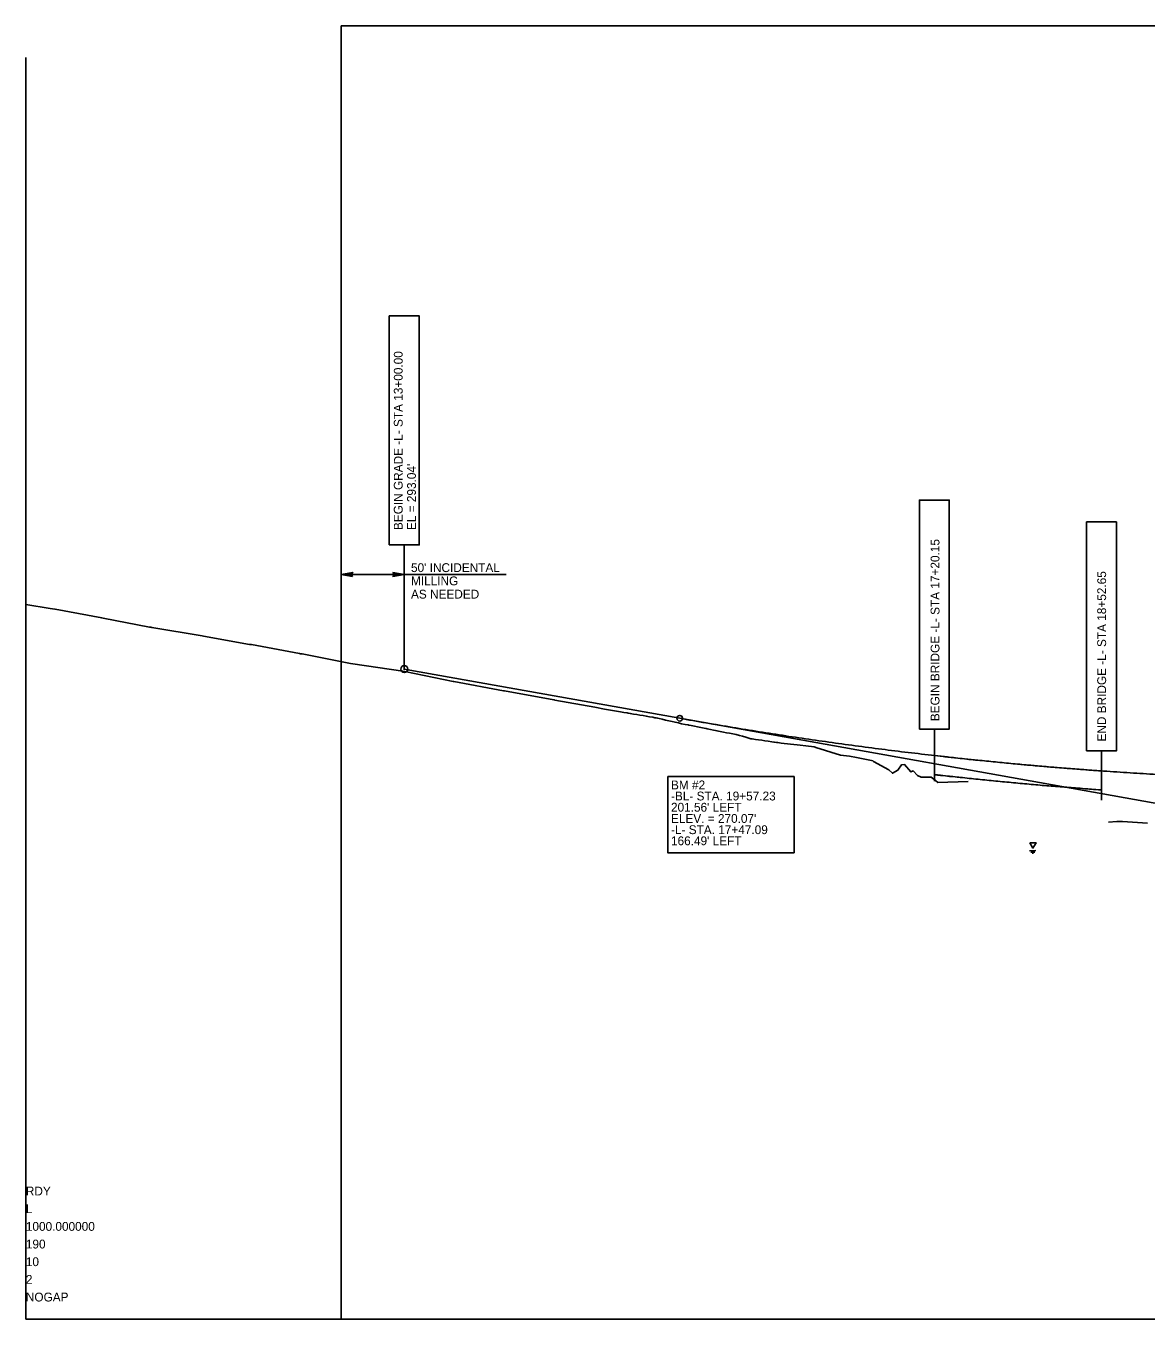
# Model space of a CAD drawing. Extents: x 10000 to 11818, y 10000 to 11025.
# Drawn here: x 10000 to 10888, y 10000 to 11025 of the extents above; entities that cross this region are included whole.
import ezdxf

# ---------------------------------------------------------------- set-up
doc = ezdxf.new("R2010")
doc.units = 0
for name, color, linetype in [('Default', 7, 'Continuous'), ('Exist Profile Cell', 7, 'Continuous'), ('Exist Vertical Profile Ground Line', 7, 'Continuous'), ('Prop Grid Mask', 7, 'Continuous'), ('Prop Hydrographic FEMA Cross Section', 7, 'Continuous'), ('Prop Shade Light', 7, 'Continuous'), ('Prop Terminator CELL', 7, 'Continuous'), ('Prop Vertical Profile Curve Label', 7, 'Continuous'), ('Prop Vertical Profile Grade', 7, 'Continuous'), ('Prop VPI Label', 7, 'Continuous'), ('Sheet Layout Profile Border', 7, 'Continuous')]:
    doc.layers.add(name, color=color, linetype=linetype)

msp = doc.modelspace()

# ---------------------------------------------------------------- linework, layer by layer
at = {"layer": 'Default'}
for p, q in [((10852.6, 10414.4), (10852.6, 10411.4)), ((10795.7, 10371.2), (10800.7, 10371.3)), ((10796.7, 10370.2), (10799.7, 10370.2)), ((10797.7, 10369.2), (10798.7, 10369.2))]:
    msp.add_line(p, q, dxfattribs=at)
msp.add_lwpolyline([(10795.8, 10377.6), (10800.8, 10377.6), (10798.3, 10373.3)], close=True, dxfattribs=at)
at = {"layer": 'Exist Profile Cell'}
for q in [(10000, 11000), (11817.5, 10000), (10000, 10000)]:
    msp.add_line((10000, 10000), q, dxfattribs=at)
at = {"layer": 'Exist Vertical Profile Ground Line'}
for p, q in [((10722.9, 10425.4), (10747, 10426)), ((10858.1, 10393.9), (10858.3, 10394))]:
    msp.add_line(p, q, dxfattribs=at)
for points in [[(10000, 10566.3), (10019.2, 10563.2), (10021.1, 10563), (10023.1, 10562.6), (10060.1, 10555.7), (10061.4, 10555.5), (10098.1, 10548.5), (10099, 10548.3), (10099.9, 10548.1), (10139.8, 10541.5), (10140.9, 10541.3), (10177.2, 10534.8), (10178.8, 10534.6), (10216.8, 10527.6), (10217.8, 10527.4), (10218.9, 10527.2), (10257.3, 10519.7), (10259.3, 10519.4), (10298.8, 10513.6), (10299.8, 10513.4), (10300.4, 10513.3), (10338.8, 10505.4), (10339.2, 10505.3), (10378.7, 10498), (10379.1, 10498), (10379.4, 10497.9), (10418.5, 10490.9), (10419, 10490.8), (10419.4, 10490.7), (10451.1, 10484.9), (10458.8, 10483.4), (10471.5, 10481.3), (10474, 10480.9), (10476.6, 10480.5), (10477.4, 10480.3), (10479.1, 10480.1), (10481.7, 10479.6), (10484.2, 10479.2), (10486.7, 10478.7), (10489.3, 10478.3), (10491.8, 10477.9), (10494.4, 10477.4), (10496.9, 10477), (10498.5, 10476.7), (10499.6, 10476.5), (10500.9, 10476.2), (10502, 10476), (10504.5, 10475.4), (10507.1, 10474.8), (10509.6, 10474.2), (10512.2, 10473.7), (10514.7, 10473.1), (10517.3, 10472.5), (10519.8, 10471.9), (10522.6, 10471.3), (10524.9, 10470.9), (10525.5, 10470.8), (10527.4, 10470.4), (10530, 10469.9), (10532.5, 10469.4), (10535.1, 10468.9), (10537.6, 10468.4), (10539.3, 10468), (10540.1, 10467.8), (10542.7, 10467.3), (10545.2, 10466.8), (10546.7, 10466.5), (10547.8, 10466.3), (10550.3, 10465.8), (10552.9, 10465.3), (10555.4, 10464.8), (10557.9, 10464.3), (10560.5, 10463.8), (10563, 10463.3), (10565.8, 10462.7), (10568.1, 10462), (10570.6, 10461.3), (10573.2, 10460.5), (10574.8, 10460), (10575.7, 10459.9), (10578.3, 10459.5), (10580.8, 10459.1), (10583.4, 10458.8), (10585.9, 10458.4), (10588.4, 10458), (10591.2, 10457.6), (10593, 10457.3), (10593.5, 10457.2), (10594.9, 10457.1), (10596.1, 10456.9), (10598.6, 10456.6), (10601.2, 10456.3), (10603.7, 10456), (10606.2, 10455.7), (10608.8, 10455.4), (10611.3, 10455.1), (10613.9, 10454.8), (10618.4, 10454.3), (10624.8, 10453.5), (10625.8, 10453.2), (10626.2, 10453.1), (10645.7, 10446.9), (10652.9, 10446.1), (10658.4, 10445.1), (10670.3, 10442.7), (10671.3, 10442.4), (10671.9, 10441.9), (10684.2, 10435.4), (10686.9, 10432.7), (10691.1, 10435), (10694.1, 10439.2), (10696.6, 10439.5), (10701.4, 10433.7), (10703.3, 10434.5), (10706.8, 10430.9), (10709.6, 10429.5), (10717.6, 10429.5), (10721.2, 10426.9), (10722.9, 10425.4)], [(10858.3, 10394), (10864.8, 10394.4), (10869.3, 10394.5), (10889, 10393.2)]]:
    msp.add_lwpolyline(points, dxfattribs=at)
at = {"layer": 'Prop Grid Mask'}
for points in [[(10288.1, 10613.6), (10311.9, 10613.6), (10311.9, 10795.1), (10288.1, 10795.1)], [(10708.3, 10467.7), (10732, 10467.7), (10732, 10649.2), (10708.3, 10649.2)], [(10840.8, 10450.4), (10864.5, 10450.4), (10864.5, 10631.9), (10840.8, 10631.9)], [(10508.8, 10430), (10609, 10430), (10609, 10369.6), (10508.8, 10369.6)]]:
    msp.add_lwpolyline(points, close=True, dxfattribs=at)
at = {"layer": 'Prop Hydrographic FEMA Cross Section'}
for p, q in [((10720.2, 10446.4), (10720.2, 10426.3)), ((10852.6, 10434.4), (10852.6, 10414.4))]:
    msp.add_line(p, q, dxfattribs=at)
at = {"layer": 'Prop Shade Light'}
for p, q in [((10720.2, 10446.7), (10720.2, 10431.3)), ((10852.6, 10419.4), (10852.6, 10434.5))]:
    msp.add_line(p, q, dxfattribs=at)
for points in [[(10852.6, 10434.5), (10846.3, 10434.9), (10839.8, 10435.4), (10833.3, 10435.9), (10826.3, 10436.4), (10819.3, 10437), (10812.3, 10437.6), (10805.3, 10438.2), (10798.3, 10438.8), (10791.3, 10439.4), (10784.3, 10440.1), (10777.3, 10440.7), (10770.3, 10441.4), (10763.3, 10442.1), (10756.3, 10442.8), (10749.3, 10443.5), (10742.3, 10444.2), (10735.3, 10445), (10728.3, 10445.8), (10728.1, 10445.8), (10728, 10445.8), (10720.2, 10446.7)], [(10720.2, 10431.3), (10734.5, 10430), (10741.1, 10429.3), (10747.7, 10428.6), (10754.8, 10427.9), (10761.8, 10427.2), (10768.8, 10426.5), (10775.9, 10425.8), (10782.9, 10425.1), (10789.9, 10424.5), (10797, 10423.8), (10804, 10423.2), (10811, 10422.6), (10818.1, 10422.1), (10825.1, 10421.5), (10832.1, 10421), (10839, 10420.4), (10845.9, 10419.9), (10852.6, 10419.4)]]:
    msp.add_open_spline(points, degree=3, dxfattribs=at)
at = {"layer": 'Prop Terminator CELL'}
for points in [[(10259, 10588.6), (10250, 10590.2), (10259.1, 10591.8), (10257.9, 10590.2)], [(10291, 10591.7), (10300, 10590.2), (10291, 10588.6), (10292.1, 10590.2)]]:
    msp.add_lwpolyline(points, close=True, dxfattribs=at)
at = {"layer": 'Prop Vertical Profile Curve Label'}
msp.add_circle((10518.3, 10476.2), 2.25, dxfattribs=at)
at = {"layer": 'Prop Vertical Profile Grade'}
for p, q in [((10300, 10515.2), (10518.3, 10476.2)), ((10720.2, 10446.7), (10720.2, 10431.6)), ((10852.6, 10434.5), (10852.6, 10419.4))]:
    msp.add_line(p, q, dxfattribs=at)
msp.add_spline([(10518.3, 10476.2), (10539.3, 10472.5), (10560.3, 10469), (10581.3, 10465.6), (10602.3, 10462.3), (10623.3, 10459.2), (10644.3, 10456.2), (10665.3, 10453.4), (10686.3, 10450.7), (10707.3, 10448.2), (10728.3, 10445.8), (10749.3, 10443.5), (10770.3, 10441.4), (10791.3, 10439.4), (10812.3, 10437.6), (10833.3, 10435.9), (10854.3, 10434.4), (10875.3, 10433), (10896.3, 10431.7), (10917.3, 10430.6), (10938.3, 10429.6), (10959.3, 10428.8), (10980.3, 10428.1), (11001.3, 10427.5), (11022.3, 10427.1), (11043.3, 10426.9), (11064.3, 10426.8), (11085.3, 10426.8), (11106.3, 10426.9), (11127.3, 10427.3), (11148.3, 10427.7), (11169.3, 10428.3), (11190.3, 10429), (11211.3, 10429.9), (11232.3, 10430.9), (11253.3, 10432.1), (11274.3, 10433.4), (11295.3, 10434.9), (11316.3, 10436.4), (11337.3, 10438.2), (11358.3, 10440.1), (11379.3, 10442.1), (11400.3, 10444.2), (11421.3, 10446.5), (11442.3, 10449), (11463.3, 10451.6), (11484.3, 10454.3), (11505.3, 10457.2), (11526.3, 10460.2), (11547.3, 10463.4), (11568.3, 10466.7)], degree=3, dxfattribs=at)
msp.add_open_spline([(10720.2, 10431.6), (10734.5, 10430), (10741.1, 10429.3), (10747.7, 10428.6), (10754.8, 10427.9), (10761.8, 10427.2), (10768.8, 10426.5), (10775.9, 10425.8), (10782.9, 10425.1), (10789.9, 10424.5), (10797, 10423.8), (10804, 10423.2), (10811, 10422.6), (10818.1, 10422.1), (10825.1, 10421.5), (10832.1, 10421), (10839, 10420.4), (10845.8, 10419.9), (10852.6, 10419.4)], degree=3, dxfattribs=at)
at = {"layer": 'Prop VPI Label'}
for p, q in [((10300, 10514.6), (10300, 10613.6)), ((10250, 10526.6), (10250, 10591.5)), ((10250, 10590.2), (10300, 10590.2)), ((10300, 10590.2), (10380.8, 10590.2)), ((10518.3, 10476.2), (11040.6, 10382.8)), ((10720.2, 10446.7), (10720.2, 10467.7)), ((10852.6, 10434.5), (10852.6, 10450.4))]:
    msp.add_line(p, q, dxfattribs=at)
msp.add_circle((10300, 10515.2), 2.75, dxfattribs=at)
at = {"layer": 'Sheet Layout Profile Border'}
msp.add_lwpolyline([(10250, 11025), (10250, 10000), (10250, 10000), (11635, 10000), (11635, 10000), (11635, 10887.5), (11635, 10887.5), (11492.5, 10887.5), (11492.5, 11025)], close=True, dxfattribs=at)

# ---------------------------------------------------------------- texts
at = {"layer": 'Exist Profile Cell'}
for s, p in [('RDY', (10000, 10098)), ('L', (10000, 10084)), ('1000.000000', (10000, 10070)), ('190', (10000, 10056)), ('10', (10000, 10042)), ('2', (10000, 10028)), ('NOGAP', (10000, 10014))]:
    msp.add_text(s, height=7, dxfattribs=at).set_placement(p)
at = {"layer": 'Prop VPI Label'}
for s, rotation, p in [('BEGIN GRADE -L- STA 13+00.00', 90, (10298.7, 10625.4)), ("EL = 293.04'", 90, (10309.2, 10625.4)), ('BEGIN BRIDGE -L- STA 17+20.15 ', 90, (10724.2, 10473.9)), ("50' INCIDENTAL", 360, (10305.3, 10592.1)), ('MILLING', 360, (10305.3, 10581.6)), ('END BRIDGE -L- STA 18+52.65', 90, (10856.3, 10457.8)), ('AS NEEDED', 360, (10305.3, 10571.1))]:
    msp.add_text(s, height=7, rotation=rotation, dxfattribs=at).set_placement(p)
for s, p in [('BM #2', (10511.4, 10419.9)), ('-BL- STA. 19+57.23', (10511.4, 10411.1)), ("201.56' LEFT", (10511.4, 10402.2)), ("ELEV. = 270.07'", (10511.4, 10393.3)), ('-L- STA. 17+47.09', (10511.4, 10384.4)), ("166.49' LEFT", (10511.4, 10375.6))]:
    msp.add_text(s, height=7, dxfattribs=at).set_placement(p)

doc.saveas('drawing.dxf')
